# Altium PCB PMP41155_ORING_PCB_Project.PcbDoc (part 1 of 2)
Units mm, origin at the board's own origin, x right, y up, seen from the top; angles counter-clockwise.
Board outline 28 x 74 mm, 6 copper layers (Top Layer, Layer 2, Layer 3, Layer 4, Layer 5, Bottom Layer), stack 1.284 mm thick; 32 components, 11 nets, 88 pads, 180 vias.
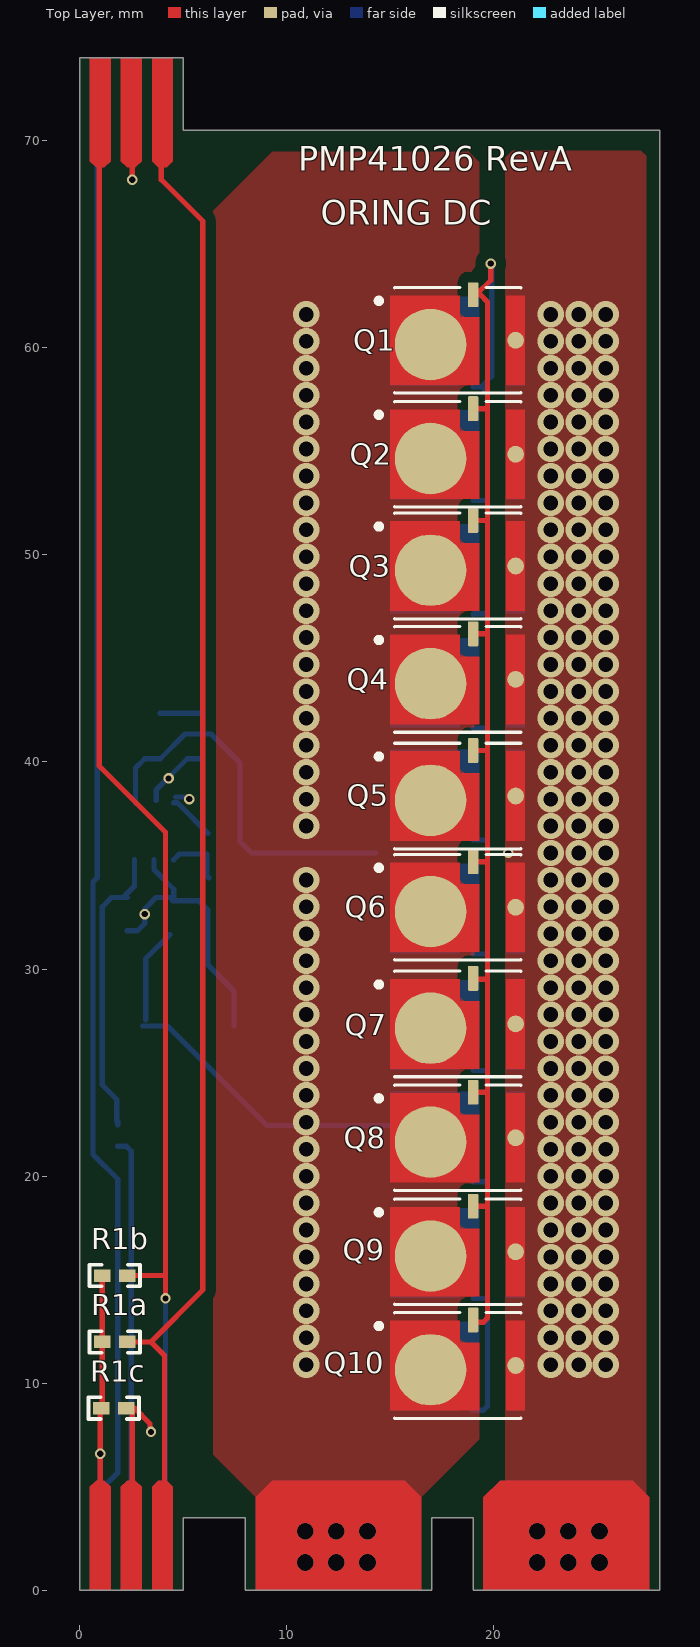
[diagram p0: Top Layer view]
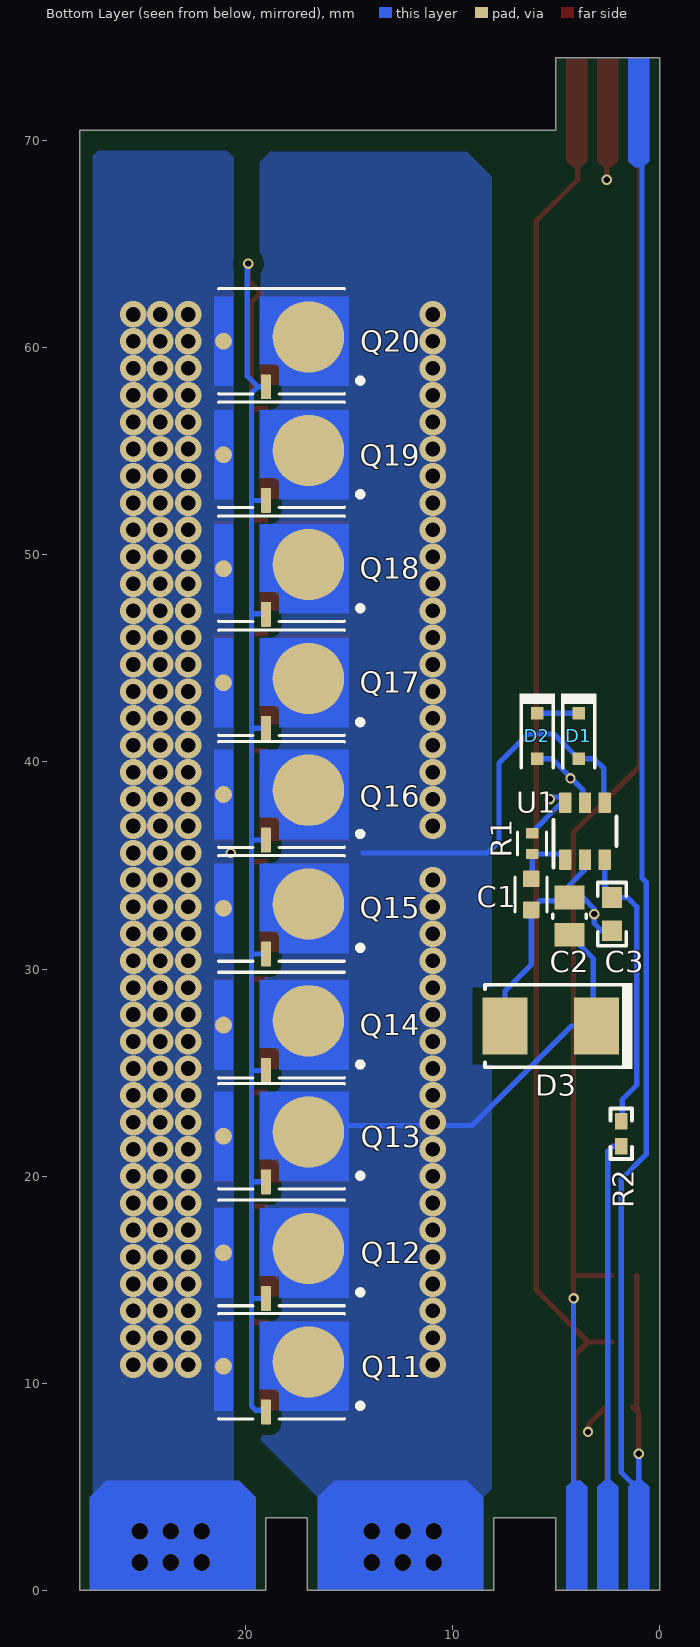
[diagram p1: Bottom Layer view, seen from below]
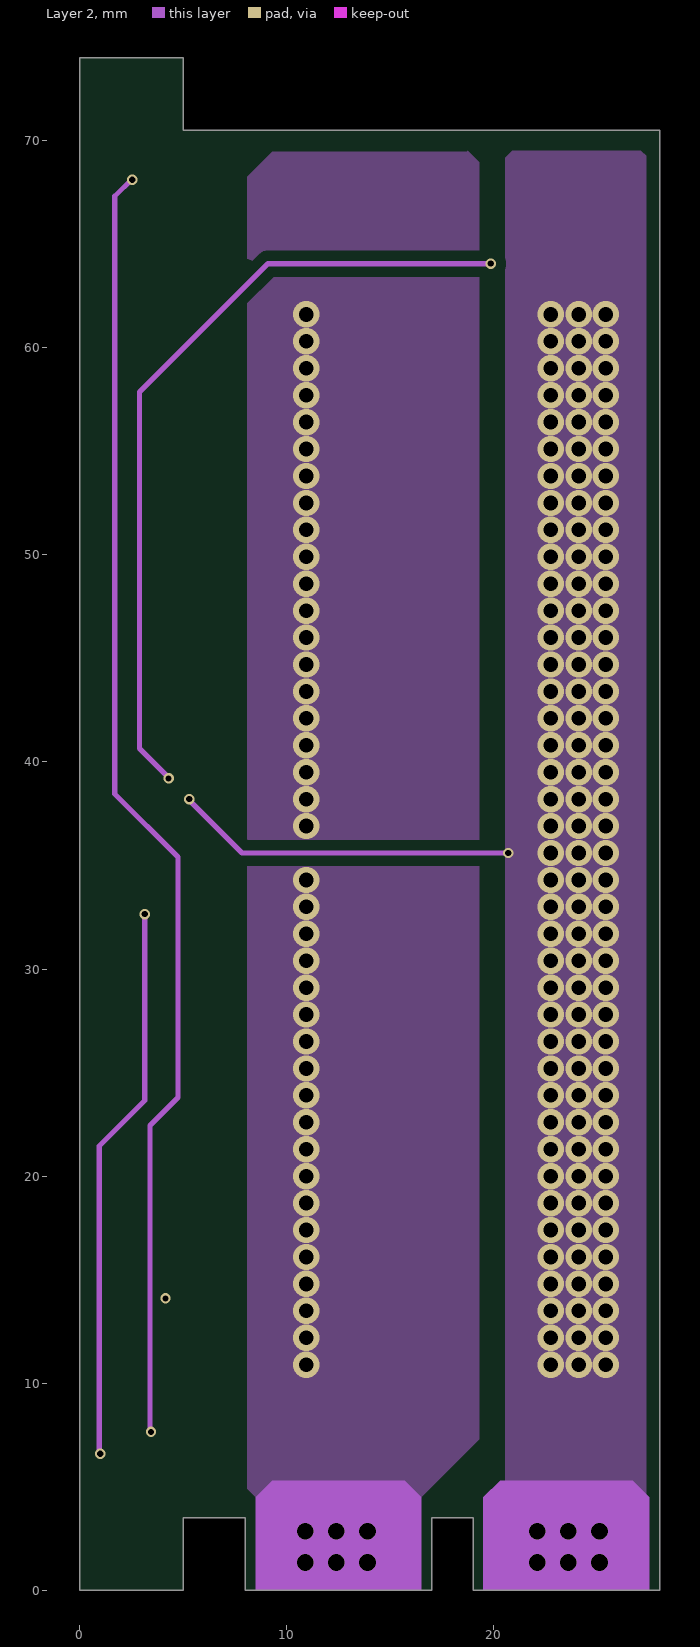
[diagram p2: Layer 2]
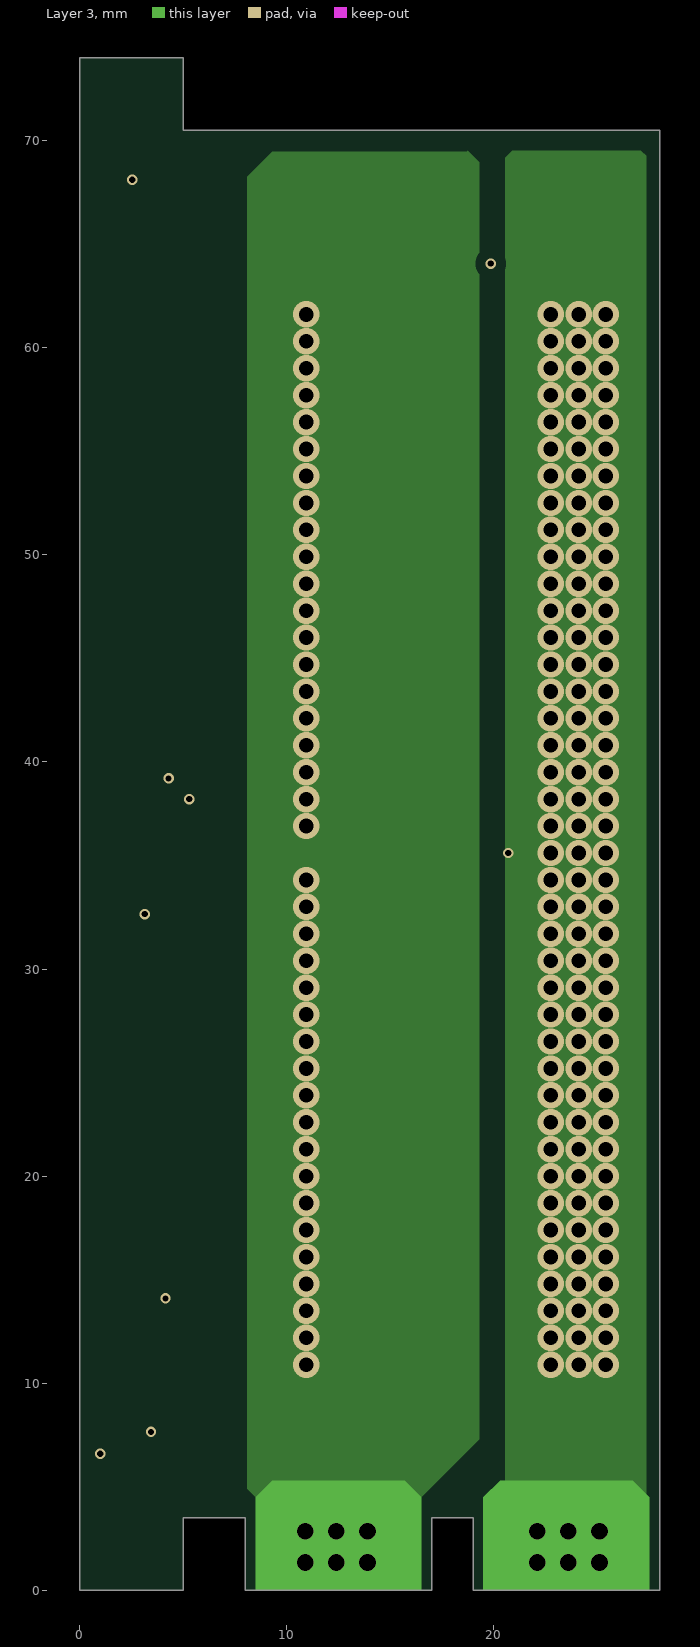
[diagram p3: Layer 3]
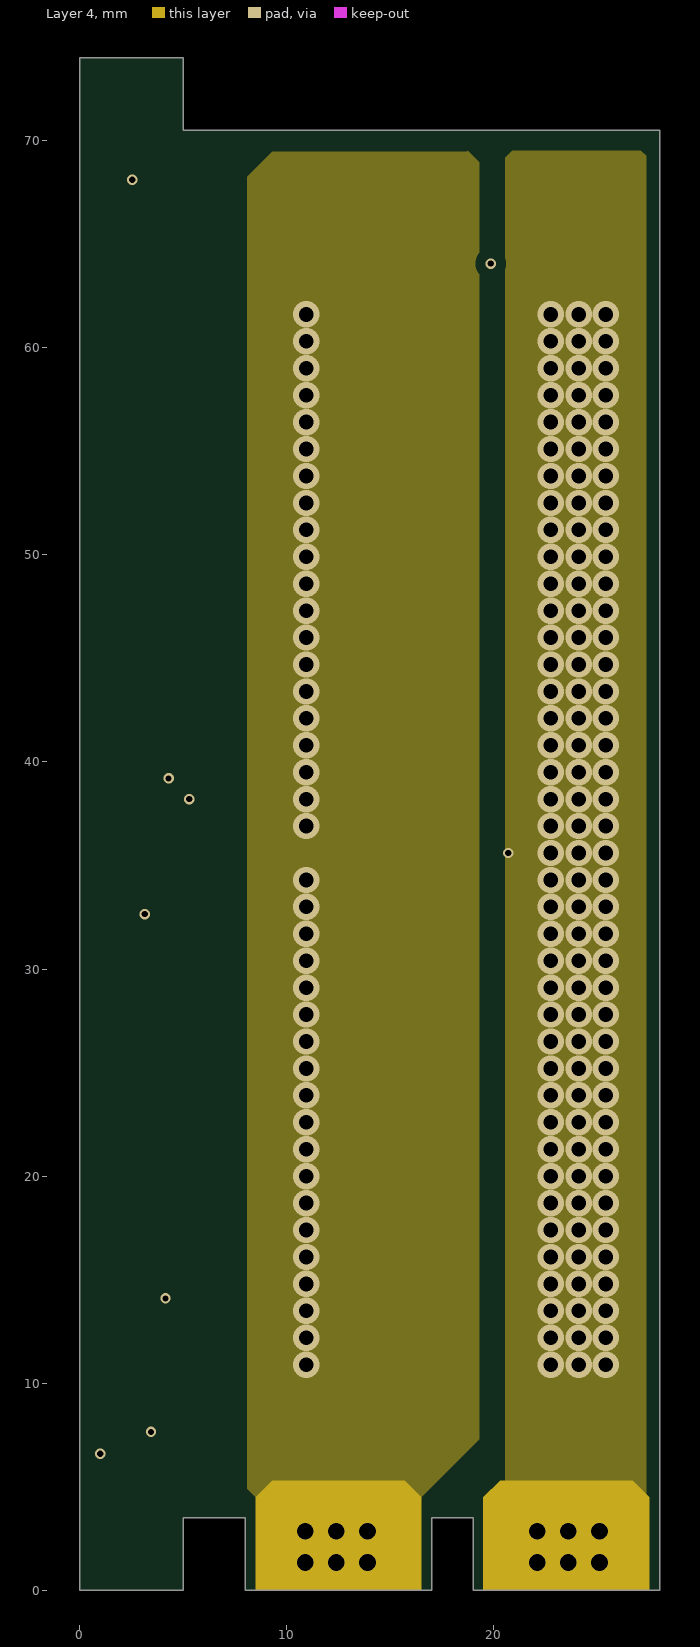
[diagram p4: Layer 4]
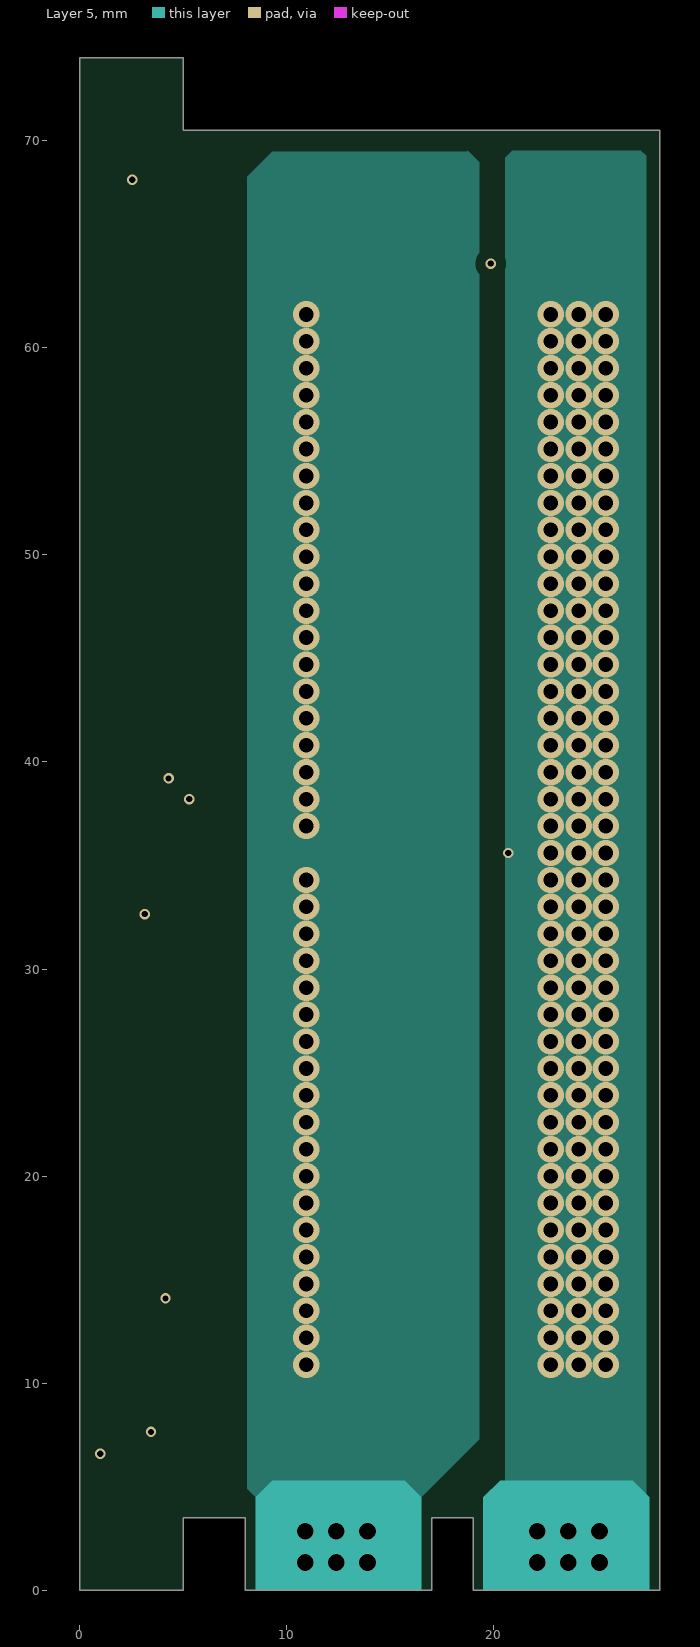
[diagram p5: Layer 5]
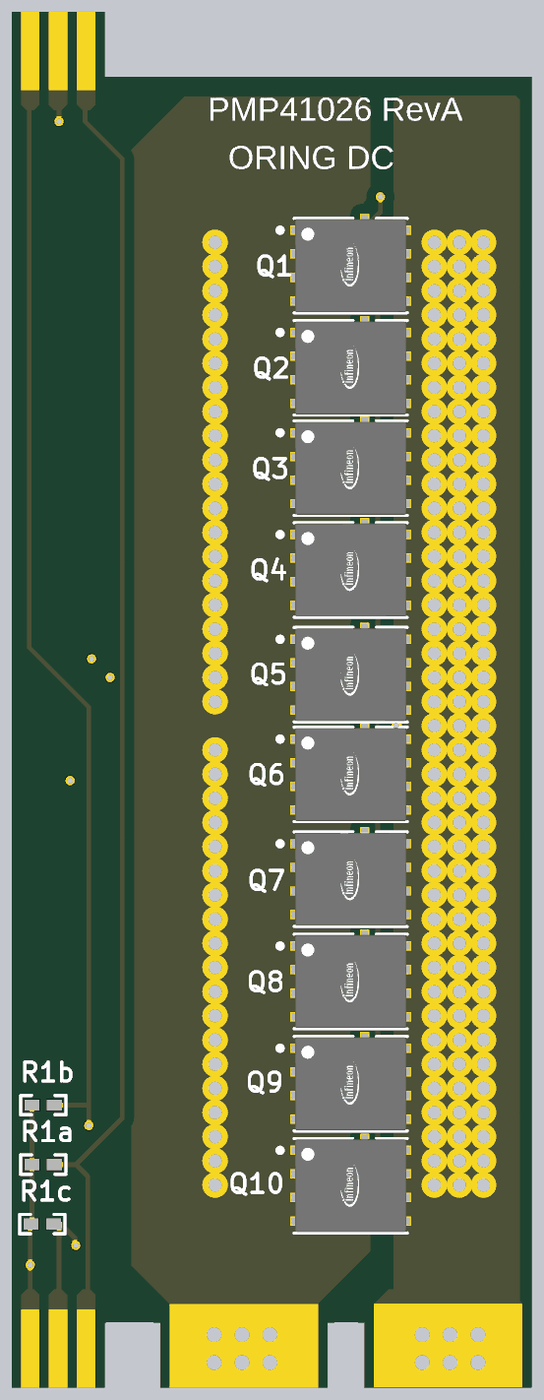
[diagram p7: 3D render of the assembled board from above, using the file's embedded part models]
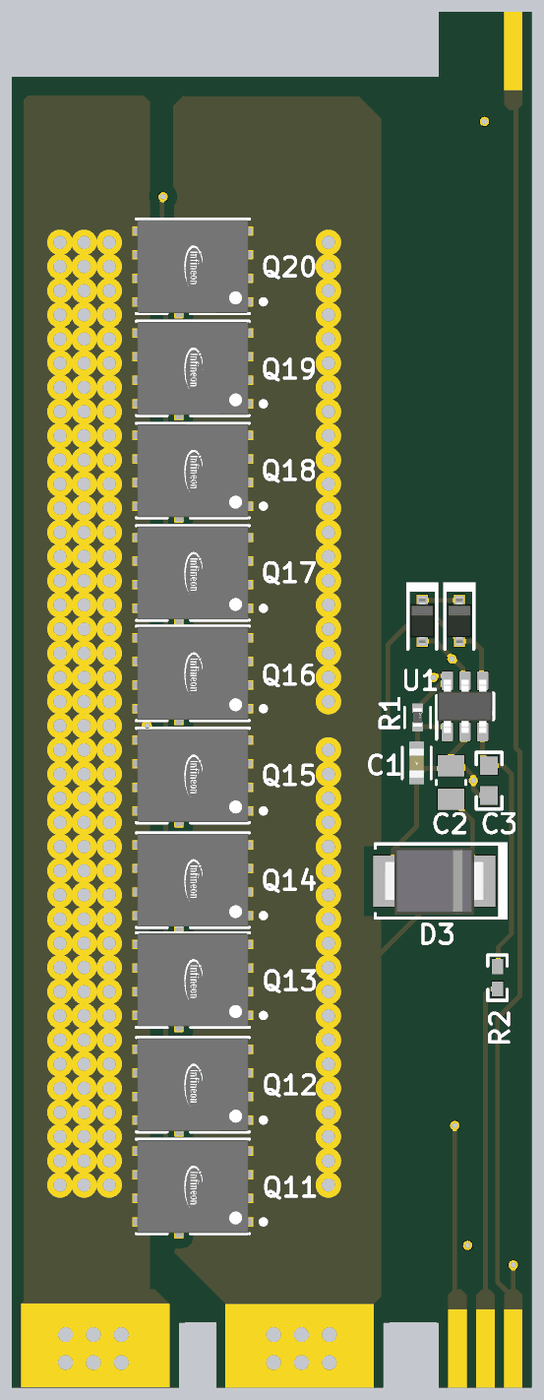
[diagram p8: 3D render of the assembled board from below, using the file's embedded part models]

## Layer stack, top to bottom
Top Solder: solder mask 0.16, Solder Resist, Dk 3.5
Top Layer: signal copper 0.07
Dielectric 1: core 0.1905, Core-023, Dk 4.2
Layer 2: signal copper 0.07
Dielectric 3: core 0.1905, Core-023, Dk 4.2
Layer 3: signal copper 0.07
Dielectric1: core 0.1016, Core-009, Dk 4.5
Layer 4: signal copper 0.07
Dielectric 4: core 0.1905, Core-023, Dk 4.2
Layer 5: signal copper 0.07
Dielectric 2: core 0.1905, Core-023, Dk 4.2
Bottom Layer: signal copper 0.07
Bottom Solder: solder mask 0.16, Solder Resist, Dk 3.5

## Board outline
0,0 0,3.5 0,74 5,74 5,70.5 28,70.5 28,13 28,0 19,0 19,3.5 17,3.5 17,0 8,0 8,3.5 5,3.5 5,0

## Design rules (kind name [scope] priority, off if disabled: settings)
AcuteAngle [All] p1: minimum=4.50000000000000E+0001 checktracksonly=FALSE
AssemblyTestPointUsage [All] p1: valid=2
Clearance Clearance_2 [InNetClass('HV') vs Not InNetClass('HV')] p1: gap=1.524 ignorepadtopadclearanceinfootprint=TRUE except(0: Arc-Hole Track-Hole SMDPad-Hole THPad-Hole Via-Hole Fill-Hole Poly-Hole Region-Hole Text-Hole)
Clearance Clearance_1 [InNetClass('MV') vs Not InNetClass('MV')] p2: gap=1.016 ignorepadtopadclearanceinfootprint=TRUE
Clearance Clearance_Keepouts [((IsTrack Or IsArc) And Not InPoly) And IsFree and IsKeepOut vs ((IsTrack Or IsArc) And Not InPoly) And IsFree and IsKeepOut] p3: gap=0 ignorepadtopadclearanceinfootprint=FALSE
Clearance Clearance_BoardEdge_MountingHoles [OnCopper and InComponentClass('Mounting Holes') vs IsKeepOut] p4: gap=1.016 ignorepadtopadclearanceinfootprint=FALSE except(0: Arc-Hole Track-Hole SMDPad-Hole THPad-Hole Via-Hole Fill-Hole Poly-Hole Region-Hole Text-Hole)
Clearance Clearance_BoardEdge_Poly [OnCopper and InPoly vs IsKeepOut] p5: gap=0.635 ignorepadtopadclearanceinfootprint=FALSE except(0: Arc-Hole Track-Hole SMDPad-Hole THPad-Hole Via-Hole Fill-Hole Poly-Hole Region-Hole Text-Hole)
Clearance Clearance_BoardEdge [OnCopper and Not InComponentClass('Logo') and not InComponentClass('FiducialMark') and not InRegion(1000,500,4000,800) and Not IsKeepout vs IsKeepOut] p6: gap=1.905 ignorepadtopadclearanceinfootprint=FALSE except(0: Arc-Hole Track-Hole SMDPad-Hole THPad-Hole Via-Hole Fill-Hole Poly-Hole Region-Hole Text-Hole)
Clearance Clearance_Poly [InPolygon] p7: gap=0.508 ignorepadtopadclearanceinfootprint=FALSE except(0: Arc-Hole Track-Hole SMDPad-Hole THPad-Hole Via-Hole Fill-Hole Poly-Hole Region-Hole Text-Hole)
Clearance [All] p8: gap=0.2 ignorepadtopadclearanceinfootprint=FALSE except(0: Arc-SMDPad Arc-Hole Track-Hole SMDPad-Hole THPad-Hole Via-Hole Fill-Hole Poly-Hole Region-Hole Text-Hole)
ComponentClearance ComponentClearance_MountingHoles_FiducialMarks [InComponentClass('Mounting Holes') vs InComponentClass('FiducialMark')] p1: gap=0.508 collisioncheckmode=3 verticalgap=0.178 showdistances=FALSE
ComponentClearance ComponentClearance_Shunt [InComponentClass('Header') vs InComponentClass('Shunt')] p2: gap=0 collisioncheckmode=3 verticalgap=0 showdistances=FALSE
ComponentClearance ComponentClearance_Logo [InComponentClass('Logo')] p3: gap=0.127 collisioncheckmode=3 verticalgap=0.254 showdistances=FALSE
ComponentClearance ComponentClearance_ScrewToNut [(HasFootprint('KEYSTONE_4824')) vs (HasFootprint('Keystone_1903C'))] p4: gap=0 collisioncheckmode=3 verticalgap=0 showdistances=FALSE
ComponentClearance ComponentClearance_MountingHoles [InComponentClass('Mounting Holes')] p5: gap=0.508 collisioncheckmode=3 verticalgap=0.178 showdistances=FALSE
ComponentClearance ComponentClearance_SmallPassives [HasFootprint('0201*') or HasFootprint('0402*') or HasFootprint('0508') or HasFootprint('0603*') or HasFootprint('0612') or HasFootprint('0805*') or HasFootprint('0815*') or HasFootprint('0830*') or HasFootprint('1206*') or HasFootprint('1210*') or HasFootprint('1808*') or HasFootprint('1812*') or HasFootprint('1825*') or HasFootprint('2010*') or HasFootprint('2220*') or HasFootprint('2225*') or HasFootprint('2512*') or HasFootprint('2728*') or HasFootprint('3518*') vs HasFootprint('0201*') or HasFootprint('0402*') or HasFootprint('0508') or HasFootprint('0603*') or HasFootprint('0612') or HasFootprint('0805*') or HasFootprint('0815*') or HasFootprint('0830*') or HasFootprint('1206*') or HasFootprint('1210*') or HasFootprint('1808*') or HasFootprint('1812*') or HasFootprint('1825*') or HasFootprint('2010*') or HasFootprint('2220*') or HasFootprint('2225*') or HasFootprint('2512*') or HasFootprint('2728*') or HasFootprint('3518*')] p6: gap=0.508 collisioncheckmode=3 verticalgap=0.508 showdistances=FALSE
ComponentClearance ComponentClearance_THtoSMT [IsThruComponent vs IsSMTComponent] p7: gap=0.254 collisioncheckmode=3 verticalgap=0.178 showdistances=FALSE
ComponentClearance ComponentClearance_THtoTH [IsThruComponent vs IsThruComponent] p8: gap=0.254 collisioncheckmode=3 verticalgap=0.178 showdistances=FALSE
ComponentClearance [All] p9: gap=0.254 collisioncheckmode=3 verticalgap=0.178 showdistances=FALSE
DiffPairsRouting [All] p1: maxlimit=2.54 minlimit=0.254 mostfreqgap=0.254 toplayer_minwidth=0.381 toplayer_maxwidth=0.381 toplayer_prefwidth=0.381 midlayer1_minwidth=0.381 midlayer1_maxwidth=0.381 midlayer1_prefwidth=0.381 midlayer2_minwidth=0.381 midlayer2_maxwidth=0.381 midlayer2_prefwidth=0.381 midlayer5_minwidth=0.381 midlayer5_maxwidth=0.381 midlayer5_prefwidth=0.381 midlayer6_minwidth=0.381 midlayer6_maxwidth=0.381 midlayer6_prefwidth=0.381 bottomlayer_minwidth=0.381 bottomlayer_maxwidth=0.381 bottomlayer_prefwidth=0.381 maxuncoupledlength=25.4
FabricationTestPointUsage TestPointUsage [All] p1: valid=2 allowmultiple=FALSE
FabricationTestpoint Testpoint [All] p1: side=3 testpointundercomponent=TRUE minsize=1.016 maxsize=2.54 preferedsize=1.524 minholesize=0 maxholesize=1.016 preferedholesize=0.813 testpointgrid=0.025 allowsidetop=TRUE allowsidebottom=TRUE usegrid=TRUE gridtolerance=0
FanoutControl Fanout_LCC [IsLCC] p1: bgadir=Out bgaviamode=Centered fanoutstyle=Auto fanoutdirection=Alternating viagrid=0.025 // Fanout_LCC (Default Rule)
FanoutControl Fanout_BGA [IsBGA] p2: bgadir=Out bgaviamode=Centered fanoutstyle=Auto fanoutdirection=Alternating viagrid=0.025 // Fanout_BGA (Default Rule)
FanoutControl Fanout_Default [All] p4: bgadir=Out bgaviamode=Centered fanoutstyle=Auto fanoutdirection=Alternating viagrid=0.025 // Fanout_Default (Default Rule)
FanoutControl Fanout_Small [(CompPinCount < 5)] p5: bgadir=Out bgaviamode=Centered fanoutstyle=Auto fanoutdirection=OutThenIn viagrid=0.025 // Fanout_Small (Default Rule)
Height [All] p1: minheight=0 maxheight=76.2 prefheight=12.7
HoleSize [All] p1: absolutevalues=TRUE maxlimit=12.725 minlimit=0.178 maxpercent=80.000 minpercent=20.000
MinimumAnnularRing MinimumAnnularRing_ThermalPadVias [IsVia and InAnyComponent] p1: minimumring=0.15
MinimumAnnularRing [All] p2: minimumring=0.127
MinimumSolderMaskSliver MinimumSolderMaskSliver_Logo [InComponentClass('Logo') vs InComponentClass('Logo')] p1: minsoldermaskwidth=0.018
MinimumSolderMaskSliver [All] p2: minsoldermaskwidth=0.025
PlaneConnect [All] p1: planeconnectstyle=Direct reliefexpansion=0.254 reliefentries=4 reliefconductorwidth=0.254 reliefairgap=0.254
PolygonConnect PolygonConnect_16 [All vs IsNamedPolygon('C106_2') Or  IsNamedPolygon('Vout') Or  IsNamedPolygon('IN+') Or  IsNamedPolygon('Q203_5') Or  IsNamedPolygon('IN+') Or  IsNamedPolygon('Q201_5') Or  IsNamedPolygon('C108_2') Or  IsNamedPolygon('SGND') Or  IsNamedPolygon('IN+') Or  IsNamedPolygon('SGND') Or  IsNamedPolygon('Q203_5') Or  IsNamedPolygon('IN+') Or  IsNamedPolygon('SGND') Or  IsNamedPolygon('GND') Or  IsNamedPolygon('C113_2') Or  IsNamedPolygon('C107_2') Or  IsNamedPolygon('C107_2') Or  IsNamedPolygon('Vout') Or  IsNamedPolygon('SIGNAL_LAYER_1_GND_P074') Or  IsNamedPolygon('HV') Or  IsNamedPolygon('C108_2') Or  IsNamedPolygon('C103_2') Or  IsNamedPolygon('Q201_5') Or  IsNamedPolygon('Vout') Or  IsNamedPolygon('C109_2') Or  IsNamedPolygon('Q201_5') Or  IsNamedPolygon('GND') Or  IsNamedPolygon('C107_2') Or  IsNamedPolygon('C102_1') Or  IsNamedPolygon('GND') Or  IsNamedPolygon('SGND') Or  IsNamedPolygon('HS') Or  IsNamedPolygon('Q203_5') Or  IsNamedPolygon('Q201_5') Or  IsNamedPolygon('Q203_5')] p1: connectstyle=Direct reliefconductorwidth=0.254 reliefentries=4 polygonreliefangle="90 Angle" airgapwidth=0.254
PolygonConnect PolygonConnect_15 [All vs IsNamedPolygon('C109_2') Or  IsNamedPolygon('C107_2') Or  IsNamedPolygon('HV') Or  IsNamedPolygon('Q203_5') Or  IsNamedPolygon('C107_2') Or  IsNamedPolygon('HS') Or  IsNamedPolygon('Q201_5') Or  IsNamedPolygon('Q203_5') Or  IsNamedPolygon('C106_2') Or  IsNamedPolygon('C108_2') Or  IsNamedPolygon('Vout') Or  IsNamedPolygon('Q203_5') Or  IsNamedPolygon('C108_2') Or  IsNamedPolygon('C113_2') Or  IsNamedPolygon('Q203_5') Or  IsNamedPolygon('Q201_5') Or  IsNamedPolygon('C107_2') Or  IsNamedPolygon('C102_1') Or  IsNamedPolygon('SGND') Or  IsNamedPolygon('GND') Or  IsNamedPolygon('SGND') Or  IsNamedPolygon('GND') Or  IsNamedPolygon('IN+') Or  IsNamedPolygon('IN+') Or  IsNamedPolygon('Q201_5') Or  IsNamedPolygon('Q201_5') Or  IsNamedPolygon('SGND') Or  IsNamedPolygon('SGND') Or  IsNamedPolygon('Vout') Or  IsNamedPolygon('Vout') Or  IsNamedPolygon('IN+') Or  IsNamedPolygon('GND') Or  IsNamedPolygon('IN+') Or  IsNamedPolygon('GND')] p2: connectstyle=Direct reliefconductorwidth=0.254 reliefentries=4 polygonreliefangle="90 Angle" airgapwidth=0.254
PolygonConnect PolygonConnect_14 [All vs IsNamedPolygon('C106_2') Or  IsNamedPolygon('C107_2') Or  IsNamedPolygon('C107_2') Or  IsNamedPolygon('C107_2') Or  IsNamedPolygon('C102_1') Or  IsNamedPolygon('Q203_5') Or  IsNamedPolygon('Vout') Or  IsNamedPolygon('Q203_5') Or  IsNamedPolygon('Q203_5') Or  IsNamedPolygon('Q201_5') Or  IsNamedPolygon('C108_2') Or  IsNamedPolygon('Q203_5') Or  IsNamedPolygon('HS') Or  IsNamedPolygon('HV') Or  IsNamedPolygon('C108_2') Or  IsNamedPolygon('Q201_5') Or  IsNamedPolygon('C109_2') Or  IsNamedPolygon('Q201_5') Or  IsNamedPolygon('Q201_5') Or  IsNamedPolygon('C113_2')] p3: connectstyle=Direct reliefconductorwidth=0.254 reliefentries=4 polygonreliefangle="90 Angle" airgapwidth=0.254
PolygonConnect PolygonConnect_13 [All vs IsNamedPolygon('C102_1') Or  IsNamedPolygon('HV') Or  IsNamedPolygon('C107_2') Or  IsNamedPolygon('C109_2') Or  IsNamedPolygon('C107_2') Or  IsNamedPolygon('C108_2') Or  IsNamedPolygon('C106_2') Or  IsNamedPolygon('C108_2') Or  IsNamedPolygon('C113_2') Or  IsNamedPolygon('C107_2')] p4: connectstyle=Direct reliefconductorwidth=0.254 reliefentries=4 polygonreliefangle="90 Angle" airgapwidth=0.254
PolygonConnect PolygonConnect_12 [All vs IsNamedPolygon('C107_2') Or  IsNamedPolygon('C113_2') Or  IsNamedPolygon('C106_2') Or  IsNamedPolygon('C107_2') Or  IsNamedPolygon('C107_2') Or  IsNamedPolygon('C102_1')] p5: connectstyle=Direct reliefconductorwidth=0.254 reliefentries=4 polygonreliefangle="90 Angle" airgapwidth=0.254
PolygonConnect PolygonConnect_11 [All vs IsNamedPolygon('C106_2') Or  IsNamedPolygon('C102_1') Or  IsNamedPolygon('C107_2') Or  IsNamedPolygon('C107_2') Or  IsNamedPolygon('C107_2')] p6: connectstyle=Direct reliefconductorwidth=0.254 reliefentries=4 polygonreliefangle="90 Angle" airgapwidth=0.254
PolygonConnect PolygonConnect_10 [All vs IsNamedPolygon('C106_2')] p7: connectstyle=Direct reliefconductorwidth=0.254 reliefentries=4 polygonreliefangle="90 Angle" airgapwidth=0.254
PolygonConnect PolygonConnect_9 [All vs IsNamedPolygon('C11_1') Or  IsNamedPolygon('Vin') Or  IsNamedPolygon('Vin') Or  IsNamedPolygon('5V') Or  IsNamedPolygon('D6_2') Or  IsNamedPolygon('Q3_3') Or  IsNamedPolygon('GND2') Or  IsNamedPolygon('GND2') Or  IsNamedPolygon('GND') Or  IsNamedPolygon('Q3_4') Or  IsNamedPolygon('12V5') Or  IsNamedPolygon('GND') Or  IsNamedPolygon('12V5') Or  IsNamedPolygon('D3_1')] p8: connectstyle=Direct reliefconductorwidth=0.254 reliefentries=4 polygonreliefangle="90 Angle" airgapwidth=0.254
PolygonConnect PolygonConnect_8 [All vs IsNamedPolygon('C11_1') Or  IsNamedPolygon('Vin') Or  IsNamedPolygon('12V5') Or  IsNamedPolygon('Q3_3') Or  IsNamedPolygon('GND2') Or  IsNamedPolygon('GND2') Or  IsNamedPolygon('5V') Or  IsNamedPolygon('Q3_4') Or  IsNamedPolygon('12V5')] p9: connectstyle=Direct reliefconductorwidth=0.254 reliefentries=4 polygonreliefangle="90 Angle" airgapwidth=0.254
PolygonConnect PolygonConnect_7 [All vs IsNamedPolygon('GND2') Or  IsNamedPolygon('GND2') Or  IsNamedPolygon('5V') Or  IsNamedPolygon('12V5') Or  IsNamedPolygon('12V5') Or  IsNamedPolygon('C11_1')] p10: connectstyle=Direct reliefconductorwidth=0.254 reliefentries=4 polygonreliefangle="90 Angle" airgapwidth=0.254
PolygonConnect PolygonConnect_6 [All vs IsNamedPolygon('GND2') Or  IsNamedPolygon('SGND') Or  IsNamedPolygon('GND1') Or  IsNamedPolygon('C901_1') Or  IsNamedPolygon('SGND') Or  IsNamedPolygon('GND2') Or  IsNamedPolygon('GND1')] p11: connectstyle=Direct reliefconductorwidth=0.254 reliefentries=4 polygonreliefangle="90 Angle" airgapwidth=0.254
PolygonConnect PolygonConnect_5 [All vs IsNamedPolygon('GND1') Or  IsNamedPolygon('GND1')] p12: connectstyle=Direct reliefconductorwidth=0.254 reliefentries=4 polygonreliefangle="90 Angle" airgapwidth=0.254
PolygonConnect PolygonConnect_4 [All vs IsNamedPolygon('C21_1') Or  IsNamedPolygon('C5_1') Or  IsNamedPolygon('C12_2') Or  IsNamedPolygon('C2_2') Or  IsNamedPolygon('C13_1') Or  IsNamedPolygon('C28_1') Or  IsNamedPolygon('C6_1') Or  IsNamedPolygon('GND') Or  IsNamedPolygon('GND2') Or  IsNamedPolygon('C14_1') Or  IsNamedPolygon('C13_1') Or  IsNamedPolygon('Q1_3') Or  IsNamedPolygon('C14_1') Or  IsNamedPolygon('C5_1') Or  IsNamedPolygon('GND2') Or  IsNamedPolygon('C28_1') Or  IsNamedPolygon('D5_2') Or  IsNamedPolygon('D6_2') Or  IsNamedPolygon('D2_1') Or  IsNamedPolygon('C12_2') Or  IsNamedPolygon('D2_1') Or  IsNamedPolygon('C4_1') Or  IsNamedPolygon('C4_1') Or  IsNamedPolygon('C2_2') Or  IsNamedPolygon('GND') Or  IsNamedPolygon('C33_1') Or  IsNamedPolygon('C9_1')] p13: connectstyle=Direct reliefconductorwidth=0.254 reliefentries=4 polygonreliefangle="90 Angle" airgapwidth=0.254
PolygonConnect PolygonConnect_3 [All vs IsNamedPolygon('C28_1') Or  IsNamedPolygon('C12_2') Or  IsNamedPolygon('C28_1') Or  IsNamedPolygon('C9_1') Or  IsNamedPolygon('D5_2') Or  IsNamedPolygon('C12_2') Or  IsNamedPolygon('C2_2') Or  IsNamedPolygon('C14_1') Or  IsNamedPolygon('C4_1') Or  IsNamedPolygon('C14_1') Or  IsNamedPolygon('D6_2') Or  IsNamedPolygon('GND2') Or  IsNamedPolygon('Q1_3') Or  IsNamedPolygon('C5_1') Or  IsNamedPolygon('D2_1') Or  IsNamedPolygon('C4_1') Or  IsNamedPolygon('C13_1') Or  IsNamedPolygon('C5_1') Or  IsNamedPolygon('C13_1') Or  IsNamedPolygon('C33_1') Or  IsNamedPolygon('D2_1') Or  IsNamedPolygon('GND') Or  IsNamedPolygon('GND') Or  IsNamedPolygon('GND2') Or  IsNamedPolygon('C2_2') Or  IsNamedPolygon('C6_1') Or  IsNamedPolygon('C21_1')] p14: connectstyle=Direct reliefconductorwidth=0.254 reliefentries=4 polygonreliefangle="90 Angle" airgapwidth=0.254
PolygonConnect PolygonConnect_2 [All vs IsNamedPolygon('C21_1') Or  IsNamedPolygon('C4_1') Or  IsNamedPolygon('D5_2') Or  IsNamedPolygon('C5_1') Or  IsNamedPolygon('C14_1') Or  IsNamedPolygon('C13_1') Or  IsNamedPolygon('C4_1') Or  IsNamedPolygon('C33_1') Or  IsNamedPolygon('C12_2') Or  IsNamedPolygon('D2_1') Or  IsNamedPolygon('C2_2') Or  IsNamedPolygon('C28_1') Or  IsNamedPolygon('C12_2') Or  IsNamedPolygon('D2_1') Or  IsNamedPolygon('C5_1') Or  IsNamedPolygon('Q1_3') Or  IsNamedPolygon('GND') Or  IsNamedPolygon('D6_2') Or  IsNamedPolygon('C6_1') Or  IsNamedPolygon('C2_2') Or  IsNamedPolygon('C14_1') Or  IsNamedPolygon('C28_1') Or  IsNamedPolygon('C13_1') Or  IsNamedPolygon('C9_1') Or  IsNamedPolygon('GND')] p15: connectstyle=Direct reliefconductorwidth=0.254 reliefentries=4 polygonreliefangle="90 Angle" airgapwidth=0.254
PolygonConnect PolygonConnect_1 [All vs IsNamedPolygon('C28_1') Or  IsNamedPolygon('D5_2') Or  IsNamedPolygon('C5_1') Or  IsNamedPolygon('C5_1') Or  IsNamedPolygon('D2_1') Or  IsNamedPolygon('C21_1') Or  IsNamedPolygon('C9_1') Or  IsNamedPolygon('C4_1') Or  IsNamedPolygon('C14_1') Or  IsNamedPolygon('C28_1') Or  IsNamedPolygon('C6_1') Or  IsNamedPolygon('C12_2') Or  IsNamedPolygon('C33_1') Or  IsNamedPolygon('C4_1') Or  IsNamedPolygon('C13_1') Or  IsNamedPolygon('C12_2') Or  IsNamedPolygon('D6_2') Or  IsNamedPolygon('C2_2') Or  IsNamedPolygon('C14_1') Or  IsNamedPolygon('D2_1') Or  IsNamedPolygon('C2_2') Or  IsNamedPolygon('C13_1')] p16: connectstyle=Direct reliefconductorwidth=0.254 reliefentries=4 polygonreliefangle="90 Angle" airgapwidth=0.254
PolygonConnect [All] p17: connectstyle=Direct reliefconductorwidth=0.254 reliefentries=4 polygonreliefangle="90 Angle" airgapwidth=0.254
RoutingLayers [All] p1: top layer_v5=TRUE mid layer 1_v5=TRUE mid layer 2_v5=TRUE mid layer 5_v5=FALSE mid layer 6_v5=FALSE bottom layer_v5=TRUE
RoutingVias ThermalPadVias [IsVia and not InNet('SGND')and not InNet('Vout')] p1: holewidth=0.2 width=0.5 viastyle="Through Hole" minholewidth=0.2 minwidth=0.5 maxholewidth=0.432 maxwidth=0.889
RoutingVias [IsVia and not InNet('SGND')and not InNet('Vout')] p2: holewidth=0.406 width=0.864 viastyle="Through Hole" minholewidth=0.2 minwidth=0.508 maxholewidth=1.016 maxwidth=1.651
SilkToBoardRegionClearance [Not ((IsComment or IsDesignator) And (Hide <> 'False')) and not InRegion(1000,500,4000,800)] p1:
SilkToSilkClearance SilkToSilkClearance_Pb-FreeLogo [(HasFootprint('Pb-Free_Overlay_Medium') OR HasFootprint('Pb-Free_Overlay_Small')) vs (HasFootprint('Pb-Free_Overlay_Medium') OR HasFootprint('Pb-Free_Overlay_Small'))] p1: silktosilkclearance=0
SilkToSilkClearance [All] p2: silktosilkclearance=0.076
SilkToSolderMaskClearance "Silk to Solder Mask Opening" [All] p1: minsilkscreentomaskgap=0.025 clearancetoexposedcopper=FALSE
SolderMaskExpansion [All] p1: expansion=0.05 istentingtop=FALSE
SupplyNets "Schematic Supply Nets" [InNet('SGND')] p1: voltage=0.000
UnpouredPolygon [All] p1: allowunpoured=TRUE allowshelved=TRUE
Width [All] p1: maxlimit=2.54 minlimit=0.152 preferedwidth=0.254 checkconnectedcopper=TRUE
12 further rules are at their usual default settings.

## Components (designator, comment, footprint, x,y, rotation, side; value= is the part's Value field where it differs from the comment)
C1 "885012206120" FP-885012206120_0603-MFG 6.2,33.6 r90 bottom value=100nF
C2 "KAF21KR72A105KU" 0805_150 4.35,32.55 r90 bottom value=1uF
C3 "GRM188R71E104KA01D" 0603 2.3,32.65 r270 bottom value=0.1uF
D1 "MMSZ5245BS-7-F" SOD-323 3.9,41.25 r270 bottom value=15V
D2 "BAS316,115" SOD-323 5.9,41.25 r270 bottom value=100V
D3 "B180B-13-F" SMB 5.25,27.25 r0 bottom value=80V
Q1 "IQD016N08NM5CGATMA1" FP-IQD016N08NM5CGATMA1_TTFN-9-MFG 18.25,60.35 r0 top
Q2 "IQD016N08NM5CGATMA1" FP-IQD016N08NM5CGATMA1_TTFN-9-MFG 18.25,54.85 r0 top
Q3 "IQD016N08NM5CGATMA1" FP-IQD016N08NM5CGATMA1_TTFN-9-MFG 18.25,49.455 r0 top
Q4 "IQD016N08NM5CGATMA1" FP-IQD016N08NM5CGATMA1_TTFN-9-MFG 18.25,43.98 r0 top
Q5 "IQD016N08NM5CGATMA1" FP-IQD016N08NM5CGATMA1_TTFN-9-MFG 18.25,38.35 r0 top
Q6 "IQD016N08NM5CGATMA1" FP-IQD016N08NM5CGATMA1_TTFN-9-MFG 18.25,32.98 r0 top
Q7 "IQD016N08NM5CGATMA1" FP-IQD016N08NM5CGATMA1_TTFN-9-MFG 18.25,27.35 r0 top
Q8 "IQD016N08NM5CGATMA1" FP-IQD016N08NM5CGATMA1_TTFN-9-MFG 18.25,21.85 r0 top
Q9 "IQD016N08NM5CGATMA1" FP-IQD016N08NM5CGATMA1_TTFN-9-MFG 18.25,16.35 r0 top
Q10 "IQD016N08NM5CGATMA1" FP-IQD016N08NM5CGATMA1_TTFN-9-MFG 18.25,10.861 r0 top
Q11 "IQD016N08NM5CGATMA1" FP-IQD016N08NM5CGATMA1_TTFN-9-MFG 18.25,10.82 r0 bottom
Q12 "IQD016N08NM5CGATMA1" FP-IQD016N08NM5CGATMA1_TTFN-9-MFG 18.25,16.295 r0 bottom
Q13 "IQD016N08NM5CGATMA1" FP-IQD016N08NM5CGATMA1_TTFN-9-MFG 18.25,21.925 r0 bottom
Q14 "IQD016N08NM5CGATMA1" FP-IQD016N08NM5CGATMA1_TTFN-9-MFG 18.25,27.295 r0 bottom
Q15 "IQD016N08NM5CGATMA1" FP-IQD016N08NM5CGATMA1_TTFN-9-MFG 18.25,32.925 r0 bottom
Q16 "IQD016N08NM5CGATMA1" FP-IQD016N08NM5CGATMA1_TTFN-9-MFG 18.25,38.425 r0 bottom
Q17 "IQD016N08NM5CGATMA1" FP-IQD016N08NM5CGATMA1_TTFN-9-MFG 18.25,43.82 r0 bottom
Q18 "IQD016N08NM5CGATMA1" FP-IQD016N08NM5CGATMA1_TTFN-9-MFG 18.25,49.32 r0 bottom
Q19 "IQD016N08NM5CGATMA1" FP-IQD016N08NM5CGATMA1_TTFN-9-MFG 18.25,54.82 r0 bottom
Q20 "IQD016N08NM5CGATMA1" FP-IQD016N08NM5CGATMA1_TTFN-9-MFG 18.25,60.309 r0 bottom
R1 "RMCF0402FT100R" FP-RMCF0402FT100R_0402-MFG 6.15,36.05 r90 bottom value=100
R1a "MCR01MZPF1001" 0402 1.7,12 r0 top value=1.00k
R1b "MCR01MZPF1001" 0402 1.7,15.2 r0 top value=1.00k
R1c "MCR01MZPF1001" 0402 1.65,8.8 r0 top value=1.00k
R2 "MCR01MZPF1001" 0402 1.85,22.05 r90 bottom value=1.00k
U1 "LM5050MK-1/NOPB" DDC0006A_N 3.6,36.65 r90 bottom

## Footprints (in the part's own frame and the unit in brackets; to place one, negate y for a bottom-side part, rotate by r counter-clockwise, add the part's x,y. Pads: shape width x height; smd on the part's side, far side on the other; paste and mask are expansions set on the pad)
0402 [mm] "0402 from SM-752 data"
  rect 0.8x0.6 smd: 1(-0.6,0) 2(0.6,0)
  silkscreen extent -1.22,-0.52 1.22,0.52, body extent -0.55,-0.3 0.55,0.3, height 0.6
0603 [mm] "0603 from SM-752 data"
  rect 1x0.95 smd: 1(-0.8,0) 2(0.8,0)
  silkscreen extent -1.52,-0.69 1.52,0.69, body extent -0.87,-0.47 0.87,0.47, height 1
0805_150 [mm] "0805 / 1.5 mm height"
  rect 1.15x1.45 smd: 1(-0.9,0) 2(0.9,0)
  silkscreen extent -0.1,-0.8 0.1,0.8, body extent -1.1,-0.72 1.1,0.72, height 1.5
DDC0006A_N [mm]
  rrect17% 1x0.6 smd: 1(-1.375,0.95) 2(-1.375,0) 3(-1.375,-0.95) 4(1.375,-0.95) 5(1.375,0) 6(1.375,0.95)
  silkscreen extent -1.75,-1.52 0.7,1.53, body extent -1.43,-1.48 1.43,1.49, height 0.92
FP-885012206120_0603-MFG [mm]
  rrect13% 0.8x0.8 smd paste+0 mask+0: 1(-0.75,0) 2(0.75,0)
  silkscreen extent -0.85,-0.77 0.85,0.77, body extent -0.8,-0.4 0.8,0.4, height 0.87
FP-IQD016N08NM5CGATMA1_TTFN-9-MFG [mm]
  round 3.455 smd paste-1000 mask-1000: 1-2-3-4(-1.302,-0.207)
  round 0.81 smd paste-1000 mask-1000: 5-6-7-8(2.8,0)
  rrect20% 0.5x1.2 smd paste-1000 mask+0: 9(0.75,2.2)
  Top Layer region: 1.05,-2.155 -3.25,-2.155 -3.25,2.155 0.1,2.155 0.1,1.105 1.05,1.105
  Top Layer region: 3.25,-2.155 2.35,-2.155 2.35,2.155 3.25,2.155
  silkscreen extent -3.92,-2.55 3.05,2.55, body extent -3.35,-2.65 3.35,2.9, height 0.25
FP-RMCF0402FT100R_0402-MFG [mm]
  rrect20% 0.5x0.6 smd paste+0 mask+0: 1(-0.5,0) 2(0.5,0)
  silkscreen extent -0.55,-0.7 0.55,0.7, body extent -0.5,-0.25 0.5,0.25, height 0.4
SMB [mm] "Molded Diode, 2-Leads, Body 5.4x3.6mm, IPC Medium Density, based on OnSemi component dimensions"
  rect 2.159x2.743 smd: 1(-2.21,0) 2(2.21,0)
  silkscreen extent -3.94,-2.08 3.17,2.08, body extent -2.7,-1.8 2.7,1.8, height 2.32
SOD-323 [mm] "NXP recommended land pattern"
  rect 0.6x0.6 smd paste-0.05: 1(-1.1,0) 2(1.1,0)
  silkscreen extent -2.06,-0.86 1.53,0.86, body extent -1.3,-0.67 1.3,0.68, height 1.1

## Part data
C1: library part CMP-0097294-1, "0.1 µF ±10% 100V Ceramic Capacitor X7R 0603 (1608 Metric)", Digikey Part Number=732-885012206120TR-ND, Manufacturer="Wurth Electronics", Mouser Part Number=710-885012206120, Operating Temperature Range="-55°C to +125°C", TempCo=15%, Temperature Characteristic=X7R, Tolerance_%=10%, ValueDisplayed=100nF
C2: library part CMP-0861070-2, "CAP, CERM, 1 µF, 100 V,+/- 10%, X7R, AEC-Q200 Grade 1, 0805", Cap_Case=0805, Manufacturer=AVX, TempCo=X7R, Tolerance_%=10%, Value2=100V, ValueDisplayed=1µF
C3: library part CMP-0007404-5, "CAP, CERM, 0.1 uF, 25 V, +/- 10%, X7R, 0603", Cap_Case=0603, Manufacturer=MuRata, Supplier Part Number 1=490-1524-1-ND, TempCo=X7R, Tolerance_%=10%, Value1=Unknown, Value2=25V, ValueDisplayed=0.1uF
D1: library part CMP-0005833-4, "Diode, Zener, 15 V, 200 mW, SOD-323", Manufacturer="Diodes Inc.", Power_W=200mW, Value1=0.2W
D2: library part CMP-0029006-2, "Diode, Ultrafast, 100 V, 0.25 A, SOD-323", Manufacturer=Nexperia, Value1=0.25A, Value2=1.4V
D3: library part CMP-0028394-2, "Diode, Schottky, 80 V, 1 A, SMB", Manufacturer="Diodes Inc.", Value1=1A, Value2=0.79V
Q1 Q2 Q3 Q4 Q5 Q6 Q7 Q8 Q9 Q10 Q11 Q12 Q13 Q14 Q15 Q16 Q17 Q18 Q19 Q20: library part CMP-0122332-1, "N-Channel 80 V 31A (Ta), 323A (Tc) 3W (Ta), 333W (Tc) Surface Mount PG-TTFN-9-U02", Digikey Part Number=448-IQD016N08NM5CGATMA1CT-ND, Drain To Source Breakdown Voltage=80V, Input Capacitace At Vds="7100pF @ 40V", Manufacturer=Infineon, Mouser Part Number=726-IQD016N08NM5CGAT, Operating Temperature Range="-55°C to +175°C", Power_W=3W, Pulse Drain Current=1292A, Typ Forward Diode Voltage=0.82V
R1: library part CMP-0094733-1, "100Ω ±1% 0.063W 0402 Thick Film Chip Resistor AEC-Q200 compliant", Manufacturer="Stackpole Electronics", Operating Temperature Range="-55°C to +155°C", Power_W=63mW, TempCo=100ppm/°C, Tolerance_%=1%
R1a R1b R1c: library part CMP-0026716-1, "RES, 1.00 k, 1%, 0.063 W, 0402", Manufacturer=Rohm, Power_W=63mW, Supplier Part Number 1=RHM1.00KLCT-ND, TempCo="100 ppm/C", Tolerance_%=1%, Value2=0.063W, Value_Code=1k00, ValueDisplayed=DNP
R2: library part CMP-0026716-1, "RES, 1.00 k, 1%, 0.063 W, 0402", Manufacturer=Rohm, Power_W=63mW, Supplier Part Number 1=RHM1.00KLCT-ND, TempCo="100 ppm/C", Tolerance_%=1%, Value2=0.063W, Value_Code=1k00, ValueDisplayed=1.00k
U1: library part CMP-0066129-2, "High Side OR-ing FET Controller, DDC0006A (SOT-23-T-6)", Alternate Manufacturer="Texas Instruments"

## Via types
v1: diameter 1.27, hole 0.711, Top Layer to Bottom Layer, 159 vias
v2: diameter 0.8, hole 0.8, Top Layer to Bottom Layer, 12 vias
v3: diameter 0.5, hole 0.3, Top Layer to Bottom Layer, 9 vias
